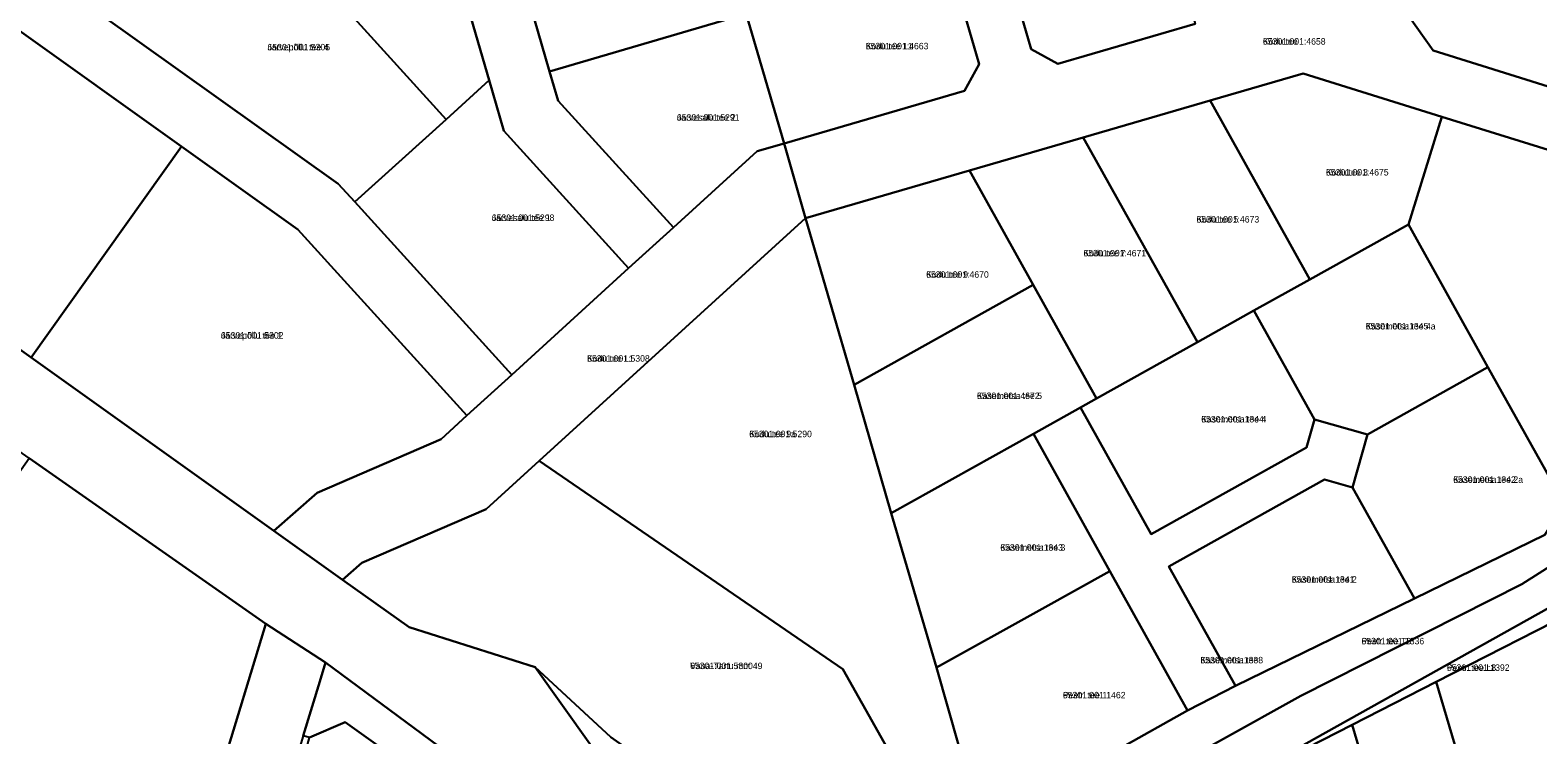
# Model space of a CAD drawing. Extents: x 543236 to 563717, y 6566033 to 6588992.
# Drawn here: x 545537.6 to 545886.5, y 6583851.3 to 6584014.2 of the extents above; entities that cross this region are included whole.
import ezdxf

# ---------------------------------------------------------------- set-up
doc = ezdxf.new("R2010")
doc.units = 0
for name, color, linetype in [('L_AADRESS', 7, 'Continuous'), ('PIIR', 7, 'Continuous'), ('TUNNUS', 7, 'Continuous')]:
    doc.layers.add(name, color=color, linetype=linetype)

msp = doc.modelspace()

# ---------------------------------------------------------------- linework, layer by layer
at = {"layer": 'PIIR'}
for points in [[(545633.92, 6583993.55), (545587.63, 6584044.56), (545623.49, 6584072.43), (545643.82, 6584002.66)], [(545849.3, 6584027.89), (545837.81, 6584044.16), (545877.65, 6584057.69), (545906.39, 6584067.18), (545914.38, 6584025.25), (545936.9, 6584018.54), (545933.7, 6584007.7), (545890.19, 6584000.82), (545862.33, 6584009.52)], [(545767.48, 6584047.12), (545795.73, 6584055.33), (545807.25, 6584015.67), (545775.45, 6584006.43), (545769.25, 6584009.83), (545761.02, 6584038.16), (545769.37, 6584040.59)], [(545657.84, 6584004.67), (545648.99, 6584035.06), (545694.56, 6584048.23), (545694.71, 6584047.67), (545703.35, 6584017.98)], [(545608.94, 6583978.69), (545553.55, 6584018.14), (545587.63, 6584044.56), (545633.92, 6583993.55), (545612.76, 6583974.48)], [(545497.57, 6583967.21), (545472.49, 6583986.81), (545509.47, 6584034.05), (545533.47, 6584015.24), (545572.68, 6583987.32), (545537.86, 6583938.49)], [(545703.35, 6584017.98), (545749.93, 6584031.53), (545757.25, 6584006.34), (545753.85, 6584000.15), (545712.13, 6583987.98)], [(545659.79, 6583997.88), (545657.84, 6584004.67), (545703.35, 6584017.98), (545712.13, 6583987.98), (545705.9, 6583986.21), (545686.51, 6583968.56)], [(545833.78, 6583956.57), (545810.7, 6583997.93), (545832.21, 6584004.18), (545864.32, 6583994.19), (545856.6, 6583969.29)], [(545649.09, 6583934.54), (545612.76, 6583974.48), (545633.92, 6583993.55), (545643.82, 6584002.66), (545647.25, 6583990.89), (545676.13, 6583959.16)], [(545781.34, 6583989.39), (545810.7, 6583997.93), (545833.78, 6583956.57), (545820.84, 6583949.35), (545807.76, 6583942.05)], [(545856.6, 6583969.29), (545864.32, 6583994.19), (545921.22, 6583976.5), (545892.62, 6583904.76), (545875, 6583936.28)], [(545755.03, 6583981.74), (545781.34, 6583989.39), (545807.76, 6583942.05), (545784.43, 6583929.04), (545769.77, 6583955.33)], [(545594.06, 6583898.45), (545537.86, 6583938.49), (545572.68, 6583987.32), (545599.6, 6583968.14), (545638.72, 6583925.1), (545632.73, 6583919.67), (545604.04, 6583907.26)], [(545609.95, 6583887.12), (545594.06, 6583898.45), (545604.04, 6583907.26), (545632.73, 6583919.67), (545638.72, 6583925.1), (545649.09, 6583934.54), (545676.13, 6583959.16), (545686.51, 6583968.56), (545705.9, 6583986.21), (545712.13, 6583987.98), (545717.08, 6583970.72), (545655.44, 6583914.6), (545643.19, 6583903.49), (545614.36, 6583891.02)], [(545717.08, 6583970.72), (545755.03, 6583981.74), (545769.77, 6583955.33), (545728.33, 6583932.19)], [(545725.73, 6583866.49), (545655.44, 6583914.6), (545717.08, 6583970.72), (545728.33, 6583932.19), (545736.91, 6583902.5), (545747.35, 6583866.82), (545752.64, 6583848.42), (545739.84, 6583841.4)], [(545820.84, 6583949.35), (545833.78, 6583956.57), (545856.6, 6583969.29), (545875, 6583936.28), (545847.12, 6583920.72), (545834.87, 6583924.2)], [(545728.33, 6583932.19), (545769.77, 6583955.33), (545784.43, 6583929.04), (545780.69, 6583926.95), (545769.79, 6583920.85), (545736.91, 6583902.5)], [(545780.69, 6583926.95), (545784.43, 6583929.04), (545807.76, 6583942.05), (545820.84, 6583949.35), (545834.87, 6583924.2), (545833.04, 6583917.74), (545797.03, 6583897.64)], [(545847.12, 6583920.72), (545875, 6583936.28), (545892.62, 6583904.76), (545888.18, 6583897.55), (545857.96, 6583882.81), (545843.64, 6583908.48)], [(545769.79, 6583920.85), (545780.69, 6583926.95), (545797.03, 6583897.64), (545833.04, 6583917.74), (545834.87, 6583924.2), (545847.12, 6583920.72), (545843.64, 6583908.48), (545837.18, 6583910.31), (545801.17, 6583890.22), (545816.57, 6583862.62), (545805.45, 6583856.88), (545787.48, 6583889.1)], [(545736.91, 6583902.5), (545769.79, 6583920.85), (545787.48, 6583889.1), (545771.85, 6583880.41), (545747.35, 6583866.82)], [(545508.09, 6583874.18), (545529.51, 6583904.2), (545537.41, 6583915.22), (545592.15, 6583876.92), (545560.92, 6583774.3), (545565.61, 6583772.85), (545562.74, 6583762.78), (545558.06, 6583764.29), (545539.89, 6583704.34), (545425.14, 6583758.05)], [(545625.34, 6583876.17), (545609.95, 6583887.12), (545614.36, 6583891.02), (545643.19, 6583903.49), (545655.44, 6583914.6), (545725.73, 6583866.49), (545739.84, 6583841.4), (545748.88, 6583825.32), (545736.57, 6583818.44), (545717.93, 6583818.36), (545672.05, 6583850.73), (545654.54, 6583866.92)], [(545801.17, 6583890.22), (545837.18, 6583910.31), (545843.64, 6583908.48), (545857.96, 6583882.81), (545816.57, 6583862.62)], [(545789.77, 6583848.12), (545805.45, 6583856.88), (545816.57, 6583862.62), (545857.96, 6583882.81), (545888.18, 6583897.55), (545892.62, 6583904.76), (545895.97, 6583898.69), (545891.7, 6583891.76), (545882.83, 6583886.14), (545831.67, 6583860.27), (545794.5, 6583839.64)], [(545654.54, 6583866.92), (545672.05, 6583850.73), (545717.93, 6583818.36), (545736.57, 6583818.44), (545748.88, 6583825.32), (545757.87, 6583830.32), (545760.63, 6583820.84), (545794.5, 6583839.64), (545831.67, 6583860.27), (545882.83, 6583886.14), (545891.7, 6583891.76), (545895.97, 6583898.69), (545906.92, 6583890.59), (545819.81, 6583841.98), (545781.61, 6583820.66), (545743.5, 6583799.39), (545741.58, 6583788.32), (545673.47, 6583840.35)], [(545747.35, 6583866.82), (545771.85, 6583880.41), (545787.48, 6583889.1), (545805.45, 6583856.88), (545789.77, 6583848.12), (545757.87, 6583830.32), (545752.64, 6583848.42)], [(545819.81, 6583841.98), (545906.92, 6583890.59), (545909.78, 6583889.8), (545908.59, 6583886.76), (545897.78, 6583881.25), (545863.02, 6583863.52), (545843.59, 6583853.61), (545822.57, 6583842.89), (545819.94, 6583841.55)], [(545863.02, 6583863.52), (545897.78, 6583881.25), (545906.01, 6583876.41), (545912.22, 6583845.32), (545872.69, 6583830.98)], [(545592.15, 6583876.92), (545605.98, 6583868.03), (545604.64, 6583863.63), (545600.82, 6583851.08), (545545.36, 6583668.74), (545511.74, 6583560.33), (545502.51, 6583547.68), (545493.29, 6583550.91), (545497.91, 6583566.14), (545507.23, 6583596.71), (545519.34, 6583636.56), (545524.6, 6583654.06), (545528.12, 6583665.67), (545539.89, 6583704.34), (545558.06, 6583764.29), (545562.74, 6583762.78), (545565.61, 6583772.85), (545560.92, 6583774.3)], [(545600.82, 6583851.08), (545604.64, 6583863.63), (545605.98, 6583868.03), (545684.18, 6583810.18), (545718.93, 6583787.19), (545847.9, 6583706.44), (545845.02, 6583702.76), (545810.78, 6583723.94), (545798.69, 6583731.38), (545767.05, 6583750.03), (545738.4, 6583767.04), (545709.1, 6583783.83), (545681.18, 6583803.25), (545646.81, 6583828.29), (545610.54, 6583854.2), (545602.25, 6583850.69)], [(545843.59, 6583853.61), (545863.02, 6583863.52), (545872.69, 6583830.98), (545879.1, 6583809.45), (545858.39, 6583803.63)], [(545602.25, 6583850.69), (545610.54, 6583854.2), (545646.81, 6583828.29), (545636.91, 6583803.26), (545630.92, 6583800.28), (545595.04, 6583824.14)], [(545822.57, 6583842.89), (545843.59, 6583853.61), (545858.39, 6583803.63), (545837.63, 6583797.8), (545835.67, 6583797.25)]]:
    msp.add_lwpolyline(points, close=True, dxfattribs=at)
for points in [[(545648.99, 6584035.06), (545657.84, 6584004.67), (545659.79, 6583997.88), (545686.51, 6583968.56), (545676.13, 6583959.16), (545647.25, 6583990.89), (545643.82, 6584002.66), (545623.49, 6584072.43)], [(545400.3, 6584043.32), (545472.49, 6583986.81), (545497.57, 6583967.21), (545537.86, 6583938.49), (545594.06, 6583898.45), (545609.95, 6583887.12), (545625.34, 6583876.17), (545654.54, 6583866.92), (545673.47, 6583840.35), (545741.58, 6583788.32), (545782.68, 6583763.62), (545794.99, 6583756.22), (545810.8, 6583746.7), (545811.77, 6583746.08), (545828.59, 6583735.35), (545856.11, 6583717.8), (545861.06, 6583714.49), (545870.11, 6583708.44), (546023.39, 6583606.64), (546139.64, 6583545.26)], [(545761.02, 6584038.16), (545769.25, 6584009.83), (545775.45, 6584006.43), (545807.25, 6584015.67)], [(545849.3, 6584027.89), (545862.33, 6584009.52), (545890.19, 6584000.82), (545933.7, 6584007.7), (545921.22, 6583976.5), (545864.32, 6583994.19), (545832.21, 6584004.18), (545810.7, 6583997.93), (545781.34, 6583989.39), (545755.03, 6583981.74), (545717.08, 6583970.72), (545712.13, 6583987.98), (545753.85, 6584000.15), (545757.25, 6584006.34), (545749.93, 6584031.53)], [(546121.63, 6583537.32), (546083.2, 6583558.43), (546036.76, 6583583.01), (546031.22, 6583585.94), (546016.86, 6583594.25), (545979.63, 6583618.27), (545847.9, 6583706.44), (545718.93, 6583787.19), (545684.18, 6583810.18), (545605.98, 6583868.03), (545592.15, 6583876.92), (545537.41, 6583915.22), (545474.84, 6583958.99), (545436.69, 6583987.47), (545399.54, 6584018.08)], [(545553.55, 6584018.14), (545608.94, 6583978.69), (545612.76, 6583974.48), (545649.09, 6583934.54), (545638.72, 6583925.1), (545599.6, 6583968.14), (545572.68, 6583987.32), (545533.47, 6584015.24)]]:
    msp.add_lwpolyline(points, dxfattribs=at)

# ---------------------------------------------------------------- texts
at = {"layer": 'L_AADRESS'}
for s, p in [('Järvepõllu tee 4', (545592.54, 6584009.52)), ('Kodu tee 11', (545731.01, 6584009.76)), ('Kodu tee', (545822.92, 6584010.85)), ('Järvesalu tee 2', (545687.29, 6583993.27)), ('Kodu tee 3', (545837.51, 6583980.59)), ('Järvesalu tee 1', (545644.45, 6583970.08)), ('Kodu tee 5', (545807.56, 6583969.71)), ('Kodu tee 7', (545781.39, 6583961.89)), ('Kodu tee 9', (545744.98, 6583956.96)), ('Järvepõllu tee 1', (545581.77, 6583942.88)), ('Kasemetsa tee 4a', (545846.7, 6583945)), ('Kodu tee L1', (545666.52, 6583937.55)), ('Kasemetsa tee 5', (545756.74, 6583928.91)), ('Kasemetsa tee 4', (545808.64, 6583923.5)), ('Kodu tee 9a', (545704.04, 6583920.09)), ('Kasemetsa tee 2a', (545866.94, 6583909.54)), ('Kasemetsa tee 3', (545762.14, 6583893.84)), ('Kasemetsa tee 2', (545829.59, 6583886.46)), ('Peetri tee T6', (545845.74, 6583872.2)), ('Vana-Tartu mnt 49', (545690.38, 6583866.48)), ('Kasemetsa tee', (545808.45, 6583867.8)), ('Peetri tee L8', (545865.5, 6583866.07)), ('Peetri tee 1', (545776.63, 6583859.71))]:
    msp.add_text(s, height=1.5, dxfattribs=at).set_placement(p)
at = {"layer": 'TUNNUS'}
for s, p in [('65301:001:5305', (545592.54, 6584009.52)), ('65301:001:4663', (545731.01, 6584009.76)), ('65301:001:4658', (545822.92, 6584010.85)), ('65301:001:5291', (545687.29, 6583993.27)), ('65301:001:4675', (545837.51, 6583980.59)), ('65301:001:5298', (545644.45, 6583970.08)), ('65301:001:4673', (545807.56, 6583969.71)), ('65301:001:4671', (545781.39, 6583961.89)), ('65301:001:4670', (545744.98, 6583956.96)), ('65301:001:5302', (545581.77, 6583942.88)), ('65301:001:1345', (545846.7, 6583945)), ('65301:001:5308', (545666.52, 6583937.55)), ('65301:001:4672', (545756.74, 6583928.91)), ('65301:001:1344', (545808.64, 6583923.5)), ('65301:001:5290', (545704.04, 6583920.09)), ('65301:001:1342', (545866.94, 6583909.54)), ('65301:001:1343', (545762.14, 6583893.84)), ('65301:001:1341', (545829.59, 6583886.46)), ('65301:001:1336', (545845.74, 6583872.2)), ('65301:001:5300', (545690.38, 6583866.48)), ('65301:001:1338', (545808.45, 6583867.8)), ('65301:001:1392', (545865.5, 6583866.07)), ('65301:001:1462', (545776.63, 6583859.71))]:
    msp.add_text(s, height=1.5, dxfattribs=at).set_placement(p)

doc.saveas('drawing.dxf')
